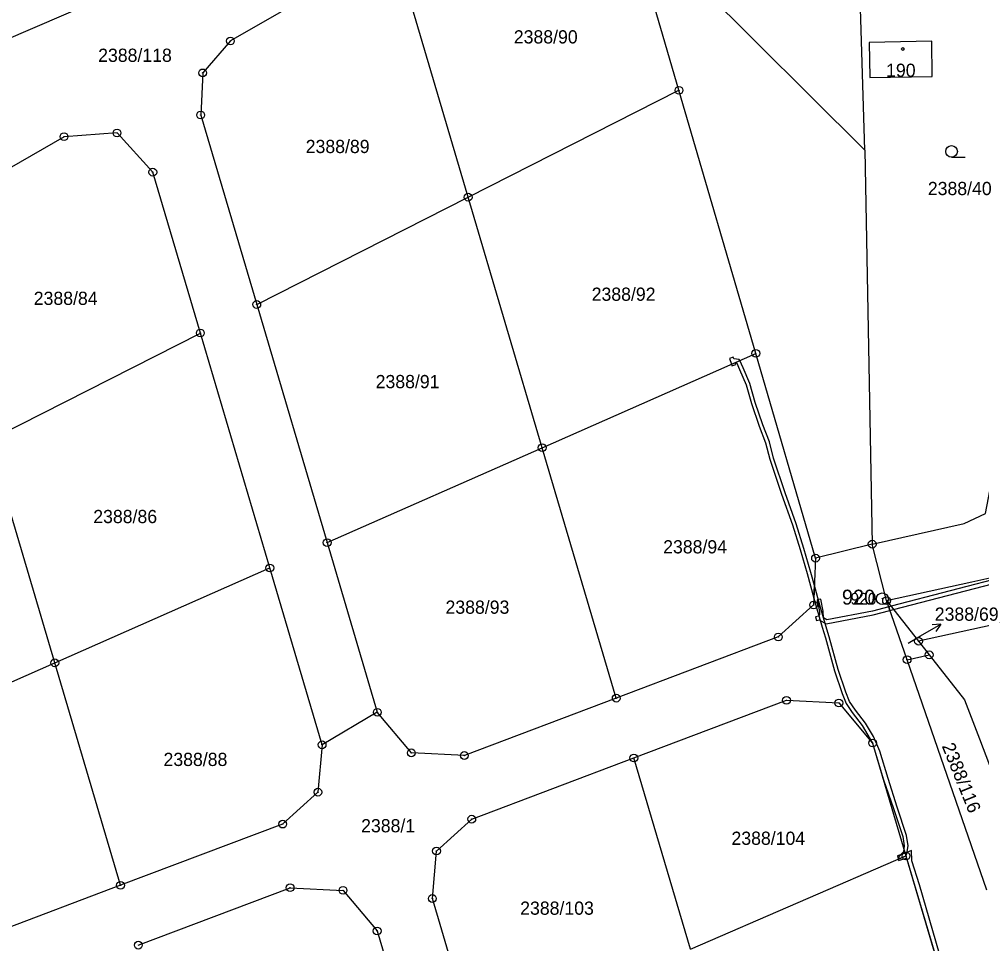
# Model space of a CAD drawing. Extents: x -758836 to -757729, y -1175316 to -1174366.
# Drawn here: x -758586.1 to -758462.2, y -1175132.2 to -1175013.2 of the extents above; entities that cross this region are included whole.
import ezdxf

# ---------------------------------------------------------------- set-up
doc = ezdxf.new("R2010")
doc.units = 0
for name, color, linetype in [('Hranice parcel', 7, 'Continuous'), ('Parcelní čísla', 7, 'Continuous'), ('Pop  PČ popisy', 7, 'Continuous'), ('Věcná břemena k části', 7, 'Continuous'), ('Značky bodu BP', 7, 'Continuous'), ('Značky budov', 7, 'Continuous'), ('Značky kultur', 7, 'Continuous')]:
    doc.layers.add(name, color=color, linetype=linetype)

msp = doc.modelspace()

# ---------------------------------------------------------------- linework, layer by layer
at = {"layer": 'Hranice parcel'}
for p, q in [((-758477.28, -1175030), (-758479.07, -1174974.04)), ((-758528.34, -1175036.07), (-758537.87, -1175003.83)), ((-758528.34, -1175036.07), (-758501.21, -1175022.31)), ((-758491.32, -1175056.18), (-758501.21, -1175022.31)), ((-758477.28, -1175030), (-758476.34, -1175080.74)), ((-758555.54, -1175049.88), (-758528.34, -1175036.07)), ((-758518.81, -1175068.32), (-758528.34, -1175036.07)), ((-758555.54, -1175049.88), (-758546.48, -1175080.54)), ((-758590, -1175067.37), (-758562.8, -1175053.56)), ((-758553.86, -1175083.8), (-758562.8, -1175053.56)), ((-758518.81, -1175068.32), (-758491.32, -1175056.18)), ((-758483.63, -1175082.55), (-758491.32, -1175056.18)), ((-758581.53, -1175096.02), (-758590, -1175067.37)), ((-758546.48, -1175080.54), (-758518.81, -1175068.32)), ((-758509.28, -1175100.57), (-758518.81, -1175068.32)), ((-758546.48, -1175080.54), (-758540.03, -1175102.38)), ((-758476.34, -1175080.74), (-758483.63, -1175082.55)), ((-758474.49, -1175088.01), (-758476.34, -1175080.74)), ((-758581.53, -1175096.02), (-758553.86, -1175083.8)), ((-758547.13, -1175106.57), (-758553.86, -1175083.8)), ((-758474.49, -1175088.01), (-758470.38, -1175093.24)), ((-758471.85, -1175095.62), (-758474.49, -1175088.01)), ((-758445.89, -1175087.81), (-758470.38, -1175093.24)), ((-758488.42, -1175092.69), (-758509.28, -1175100.57)), ((-758470.38, -1175093.24), (-758469.01, -1175094.99)), ((-758609.21, -1175108.24), (-758581.53, -1175096.02)), ((-758573.07, -1175124.66), (-758581.53, -1175096.02)), ((-758471.85, -1175095.62), (-758469.01, -1175094.99)), ((-758461.57, -1175125.29), (-758471.85, -1175095.62)), ((-758509.28, -1175100.57), (-758528.82, -1175107.95)), ((-758540.03, -1175102.38), (-758547.13, -1175106.57)), ((-758499.74, -1175132.86), (-758507.01, -1175108.26)), ((-758552.21, -1175116.78), (-758573.07, -1175124.66)), ((-758499.74, -1175132.86), (-758472, -1175120.88)), ((-758472, -1175120.88), (-758465.13, -1175144.13)), ((-758573.07, -1175124.66), (-758592.6, -1175132.04))]:
    msp.add_line(p, q, dxfattribs=at)
for points in [[(-758508.47, -1174971.76), (-758506.08, -1174993.49), (-758498.33, -1175009.04), (-758477.28, -1175030)], [(-758633.16, -1175038.79), (-758629.62, -1175031.39), (-758600.05, -1175021.05), (-758568.41, -1175007.42), (-758540.08, -1174988.98)], [(-758501.21, -1175022.31), (-758508.18, -1174998.44), (-758513.01, -1174993.13), (-758520.17, -1174993.64), (-758537.87, -1175003.83)], [(-758537.87, -1175003.83), (-758558.93, -1175015.96), (-758562.5, -1175020.07), (-758562.75, -1175025.5), (-758555.54, -1175049.88)], [(-758468.62, -1175020.52), (-758468.67, -1175016), (-758476.75, -1175016.17), (-758476.64, -1175020.68), (-758468.62, -1175020.52)], [(-758562.8, -1175053.56), (-758568.92, -1175032.85), (-758573.52, -1175027.8), (-758580.34, -1175028.28), (-758598.46, -1175038.72)], [(-758476.34, -1175080.74), (-758464.51, -1175078.07), (-758461.75, -1175076.79), (-758459.42, -1175064.46)], [(-758483.63, -1175082.55), (-758483.88, -1175088.57), (-758488.42, -1175092.69)], [(-758474.49, -1175088.01), (-758463.5, -1175085.57), (-758451.15, -1175082.83)], [(-758469.01, -1175094.99), (-758464.45, -1175100.79), (-758462.53, -1175105.82), (-758455.74, -1175123.64)], [(-758507.01, -1175108.26), (-758487.37, -1175100.84), (-758480.63, -1175101.18), (-758476.29, -1175106.35), (-758472, -1175120.88)], [(-758528.82, -1175107.95), (-758535.64, -1175107.61), (-758540.03, -1175102.38)], [(-758547.13, -1175106.57), (-758547.67, -1175112.67), (-758552.21, -1175116.78)], [(-758527.48, -1175144.85), (-758532.94, -1175126.36), (-758532.41, -1175120.25), (-758527.87, -1175116.14), (-758507.01, -1175108.26)], [(-758570.79, -1175132.36), (-758551.25, -1175124.97), (-758544.44, -1175125.31), (-758540.05, -1175130.54), (-758534.96, -1175147.77)]]:
    msp.add_lwpolyline(points, dxfattribs=at)
at = {"layer": 'Pop  PČ popisy'}
for p, q in [((-758470.12, -1175092.56), (-758467.52, -1175091.06)), ((-758467.52, -1175091.06), (-758468.64, -1175091.13)), ((-758467.52, -1175091.06), (-758468.14, -1175091.99)), ((-758471.71, -1175093.47), (-758470.12, -1175092.56))]:
    msp.add_line(p, q, dxfattribs=at)
at = {"layer": 'Věcná břemena k části'}
for points in [[(-758483.84, -1175087.71), (-758483.78, -1175086.06), (-758484.23, -1175084.39), (-758485.15, -1175081.29), (-758486.12, -1175078.11), (-758487.52, -1175074.14), (-758489.03, -1175069.67), (-758489.57, -1175067.55), (-758490.4, -1175065.38), (-758491.38, -1175062.51), (-758492.08, -1175060.05), (-758492.94, -1175058.05), (-758493.38, -1175057.09), (-758493.44, -1175056.95), (-758494.16, -1175056.89), (-758494.23, -1175056.68), (-758494.7, -1175056.83), (-758494.46, -1175057.57), (-758494.39, -1175057.78), (-758493.91, -1175057.62), (-758494, -1175057.36), (-758493.78, -1175057.43), (-758493.4, -1175058.25), (-758492.56, -1175060.21), (-758491.86, -1175062.65), (-758490.88, -1175065.54), (-758490.05, -1175067.71), (-758489.51, -1175069.81), (-758488, -1175074.3), (-758486.6, -1175078.27), (-758485.63, -1175081.43), (-758484.71, -1175084.53)], [(-758445.89, -1175087.81), (-758445.64, -1175087.73), (-758447.38, -1175082.35), (-758448.16, -1175081.88), (-758451.15, -1175082.83), (-758455.97, -1175083.9), (-758458.7, -1175084.76), (-758473.92, -1175088.73), (-758474.21, -1175088.81), (-758474.05, -1175089.28), (-758473.59, -1175089.16), (-758458.56, -1175085.24), (-758455.84, -1175084.38), (-758451.02, -1175083.31), (-758448.23, -1175082.43), (-758447.8, -1175082.69), (-758446.23, -1175087.88)], [(-758472.75, -1175121.2), (-758472, -1175120.88), (-758471.87, -1175120.56), (-758471.71, -1175119.59), (-758471.93, -1175118.25), (-758473.13, -1175114.62), (-758474.28, -1175110.92), (-758475.34, -1175107.38), (-758476.17, -1175105.5), (-758477.2, -1175103.79), (-758478.5, -1175102.12), (-758479.27, -1175101), (-758479.74, -1175099.78), (-758480.73, -1175096.89), (-758481.89, -1175092.66), (-758482.3, -1175091.27), (-758483.08, -1175088.61), (-758483.78, -1175086.06), (-758483.84, -1175087.71), (-758483.56, -1175088.75), (-758482.78, -1175091.41), (-758482.37, -1175092.8), (-758481.21, -1175097.03), (-758480.2, -1175099.96), (-758479.71, -1175101.24), (-758478.9, -1175102.42), (-758477.62, -1175104.07), (-758476.29, -1175106.35), (-758474.89, -1175111.1), (-758473.61, -1175114.78), (-758472.41, -1175118.37), (-758472.21, -1175119.59), (-758472.27, -1175119.96), (-758472.33, -1175120.34), (-758472.95, -1175121.02)], [(-758483.15, -1175090.48), (-758482.27, -1175090.99), (-758476.22, -1175089.84), (-758474.05, -1175089.28), (-758474.21, -1175088.81), (-758476.32, -1175089.36), (-758482.17, -1175090.47), (-758482.6, -1175090.22), (-758482.63, -1175089.36), (-758482.94, -1175087.82), (-758483.43, -1175087.92), (-758483.13, -1175089.42), (-758483.11, -1175089.79), (-758483.26, -1175089.99), (-758483.65, -1175090.1), (-758483.52, -1175090.58)]]:
    msp.add_lwpolyline(points, close=True, dxfattribs=at)
msp.add_lwpolyline([(-758457.77, -1175167.24), (-758464.65, -1175143.99), (-758470.26, -1175124.61), (-758471.23, -1175121.5), (-758471.28, -1175120.18), (-758472.1, -1175120.53), (-758473.1, -1175120.87), (-758472.98, -1175121.3), (-758472.94, -1175121.45), (-758471.91, -1175121.17), (-758465.13, -1175144.13), (-758458.36, -1175167)], dxfattribs=at)
at = {"layer": 'Značky bodu BP'}
for centre, radius in [((-758558.93, -1175015.96), 0.5), ((-758558.93, -1175015.96), 0.0303), ((-758562.5, -1175020.07), 0.5), ((-758562.5, -1175020.07), 0.0303), ((-758501.21, -1175022.31), 0.5), ((-758501.21, -1175022.31), 0.0303), ((-758562.75, -1175025.5), 0.5), ((-758562.75, -1175025.5), 0.0303), ((-758580.34, -1175028.28), 0.5), ((-758573.52, -1175027.8), 0.5), ((-758573.52, -1175027.8), 0.0303), ((-758580.34, -1175028.28), 0.0303), ((-758568.92, -1175032.85), 0.5), ((-758568.92, -1175032.85), 0.0303), ((-758528.34, -1175036.07), 0.5), ((-758528.34, -1175036.07), 0.0303), ((-758555.54, -1175049.88), 0.5), ((-758555.54, -1175049.88), 0.0303), ((-758562.8, -1175053.56), 0.5), ((-758562.8, -1175053.56), 0.0303), ((-758491.32, -1175056.18), 0.5), ((-758491.32, -1175056.18), 0.0303), ((-758518.81, -1175068.32), 0.5), ((-758518.81, -1175068.32), 0.0303), ((-758546.48, -1175080.54), 0.5), ((-758546.48, -1175080.54), 0.0303), ((-758476.34, -1175080.74), 0.5), ((-758476.34, -1175080.74), 0.0303), ((-758483.63, -1175082.55), 0.5), ((-758553.86, -1175083.8), 0.5), ((-758483.63, -1175082.55), 0.0303), ((-758553.86, -1175083.8), 0.0303), ((-758475.04, -1175087.77), 0.75), ((-758483.88, -1175088.57), 0.5), ((-758483.88, -1175088.57), 0.0303), ((-758475.04, -1175087.77), 0.03), ((-758474.49, -1175088.01), 0.5), ((-758474.49, -1175088.01), 0.0303), ((-758488.42, -1175092.69), 0.5), ((-758488.42, -1175092.69), 0.0303), ((-758470.38, -1175093.24), 0.5), ((-758470.38, -1175093.24), 0.0303), ((-758469.01, -1175094.99), 0.5), ((-758581.53, -1175096.02), 0.5), ((-758581.53, -1175096.02), 0.0303), ((-758471.85, -1175095.62), 0.5), ((-758471.85, -1175095.62), 0.0303), ((-758469.01, -1175094.99), 0.0303), ((-758509.28, -1175100.57), 0.5), ((-758509.28, -1175100.57), 0.0303), ((-758487.37, -1175100.84), 0.5), ((-758487.37, -1175100.84), 0.0303), ((-758480.63, -1175101.18), 0.5), ((-758540.03, -1175102.38), 0.5), ((-758480.63, -1175101.18), 0.0303), ((-758540.03, -1175102.38), 0.0303), ((-758476.29, -1175106.35), 0.5), ((-758547.13, -1175106.57), 0.5), ((-758547.13, -1175106.57), 0.0303), ((-758535.64, -1175107.61), 0.5), ((-758476.29, -1175106.35), 0.0303), ((-758535.64, -1175107.61), 0.0303), ((-758528.82, -1175107.95), 0.5), ((-758528.82, -1175107.95), 0.0303), ((-758507.01, -1175108.26), 0.5), ((-758507.01, -1175108.26), 0.0303), ((-758547.67, -1175112.67), 0.5), ((-758547.67, -1175112.67), 0.0303), ((-758527.87, -1175116.14), 0.5), ((-758552.21, -1175116.78), 0.5), ((-758552.21, -1175116.78), 0.0303), ((-758527.87, -1175116.14), 0.0303), ((-758532.41, -1175120.25), 0.5), ((-758532.41, -1175120.25), 0.0303), ((-758472, -1175120.88), 0.5), ((-758472, -1175120.88), 0.0303), ((-758573.07, -1175124.66), 0.5), ((-758551.25, -1175124.97), 0.5), ((-758573.07, -1175124.66), 0.0303), ((-758551.25, -1175124.97), 0.0303), ((-758544.44, -1175125.31), 0.5), ((-758544.44, -1175125.31), 0.0303), ((-758532.94, -1175126.36), 0.5), ((-758532.94, -1175126.36), 0.0303), ((-758540.05, -1175130.54), 0.5), ((-758540.05, -1175130.54), 0.0303), ((-758570.79, -1175132.36), 0.5)]:
    msp.add_circle(centre, radius, dxfattribs=at)
at = {"layer": 'Značky budov'}
msp.add_circle((-758472.41, -1175016.99), 0.175, dxfattribs=at)
at = {"layer": 'Značky kultur'}
msp.add_line((-758466.13, -1175030.93), (-758464.38, -1175030.93), dxfattribs=at)
msp.add_circle((-758466.13, -1175030.18), 0.75, dxfattribs=at)

# ---------------------------------------------------------------- texts
at = {"layer": 'Parcelní čísla'}
for s, p in [('2388/90', (-758522.46, -1175016.28)), ('2388/118', (-758575.95, -1175018.65)), ('190', (-758474.55, -1175020.58)), ('2388/89', (-758549.24, -1175030.39)), ('2388/40', (-758469.18, -1175035.8)), ('2388/92', (-758512.44, -1175049.41)), ('2388/84', (-758584.24, -1175049.94)), ('2388/91', (-758540.24, -1175060.66)), ('2388/86', (-758576.58, -1175078.03)), ('2388/94', (-758503.24, -1175081.93)), ('2388/93', (-758531.25, -1175089.7)), ('2388/69', (-758468.29, -1175090.6)), ('2388/88', (-758567.54, -1175109.3)), ('2388/1', (-758542.11, -1175117.84)), ('2388/104', (-758494.45, -1175119.45)), ('2388/103', (-758521.64, -1175128.45))]:
    msp.add_text(s, height=1.7, dxfattribs=at).set_placement(p)
msp.add_text('2388/116', height=1.7, rotation=292, dxfattribs=at).set_placement((-758467.41, -1175106.72))
at = {"layer": 'Značky bodu BP'}
for height, p in [(1.919, (-758480.24, -1175088.52)), (1.5, (-758479.14, -1175088.52))]:
    msp.add_text('920', height=height, dxfattribs=at).set_placement(p)

doc.saveas('drawing.dxf')
